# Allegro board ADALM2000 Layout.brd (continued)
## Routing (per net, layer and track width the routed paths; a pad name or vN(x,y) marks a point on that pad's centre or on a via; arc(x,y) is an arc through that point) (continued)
-6V0_AWG_A: length 13.4
  TOP w0.305: v1(25.5,35.06) 25.5,34.87 25.77,34.61 A9.5 ; v1(25.5,28.76) A7.5
  TOP w0.406: v1(25.5,35.06) v1(25.5,35.82)
  BOTTOM w0.305: C273.2 26.2,36.93 ; C273.2 25.71,36.4 ; C273.2 C259.2 ; 24.67,35.56 C275.2 ; C275.2 24.67,36.47 ; C275.2 25.08,36.01 ; 25.71,35.38 C259.2 ; C259.2 26.2,34.74 ; 25.08,35 C277.2 24.67,35.46 ; v1(28.8,29.35) C271.2 27.15,29.35 27.03,29.47 C265.2 C269.2 25.37,28.89 v1(25.5,28.76) ; 24.74,36.64 E13.2 25.35,37.18
-6V0_SC_A: length 34.1
  TOP w0.305: A1.4 27.21,41.93 v1(27.15,41.98) ; v1(27.15,53.92) 27.21,53.87 A4.4 ; v1(25.73,50.93) C81.1 26.51,50.81 C82.1 C83.1 28.44,51.08 v1(28.8,51.08) ; 15.47,49.72 E5.1 16.08,50.26
  BOTTOM w0.305: 29.41,37.47 C138.1 ; C138.1 30.48,37.47 30.73,37.22 C139.1 ; C138.1 29.94,37.96 ; C327.1 20.24,49.61 ; C327.1 19.66,49.06 ; C327.1 19.07,49.61 ; C90.1 33.91,47.12 ; C90.1 32.84,47.12 ; C90.1 33.37,47.62 ; 33.95,48.5 U8.1 ; U8.1 35.7,48.5 U8.PAD ; U8.1 34.7,48.07 ; v1(27.15,41.98) 26.83,42.3 C127.1 C125.1 24.86,42.3 C124.1 v1(23.98,42.18) ; C140.1 32.8,37.22 33.33,36.69 U9.1 34.81,36.69 U9.PAD ; C140.1 32.42,37.63 ; C140.1 31.98,37.22 v1(31.79,37.41) 31.6,37.22 C139.1 ; C139.1 31.15,37.63 ; 33.4,47.94 C93.1 ; C93.1 C91.1 ; C93.1 33.86,48.35 ; v1(23.98,53.86) C67.1 24.86,53.99 C68.1 C70.1 27.09,53.99 v1(27.15,53.92) ; A2.4 28.86,51.14 v1(28.8,51.08) ; C91.1 32.05,48.35 ; C91.1 32.51,47.94
  BOTTOM w0.508: 18.77,49.48 VR1.2
  vias: v1(15.21,49.35) v1(15.97,49.35) v1(20.55,49.73) v1(20.55,49.1) v1(30.39,38.17) v1(31.09,38.17) v1(31.79,38.17) v1(32.36,47.06) v1(32.36,46.43)
-6V0_USR_A: length 14.5
  TOP w0.305: v1(12.93,5.79) 13.05,5.92 A14.2 ; 12.37,5.09 C216.2 11.91,5.5 ; 12.47,5.09 C283.2 12.93,5.5
  BOTTOM w0.305: C133.2 13.05,5.58 ; C133.2 12.52,5.08 ; C133.2 13.59,5.08 ; 20.41,6.3 E16.2 20.95,6.91 ; v1(20.17,7.19) 20.17,8.58 21.82,10.23 R147.2 ; 11.38,5.08 C24.2 ; C24.2 11.91,5.58 ; C24.2 12.44,5.08
  vias: v1(11.91,5.79) v1(20.93,7.19)
GND: length 1042.3
  TOP w0.152: U509.8 U509.PAD
  TOP w0.203: D741.A v1(102.78,35.65) ; v2(38.4,46.96) 38.23,46.96 37.69,46.43 37.69,45.16 38.23,44.63 v2(38.4,44.63) ; 35.65,14.58 U7.4 ; U7.4 36.05,15.3 ; U7.4 36.05,13.87 ; v1(102.72,34.35) D739.A ; U509.PAD 101.25,31.44 U509.4 102.38,30.31 v2(102.41,30.31) ; v1(83.16,57.1) 82.62,56.56 U6.1
  TOP w0.254: U12.5 44.95,11.12 ; U12.5 44.95,9.8 ; U12.5 44.57,10.46 ; v1(64.57,60.32) 64.63,60.39 U14.11 ; U2.5 59.29,49.06 59.58,49.35 v1(59.79,49.35) ; v1(63.35,49.86) 63.35,50.07 63.59,50.31 U2.62 ; U14.15 64.32,59.76 v1(64.57,59.51) ; v1(65.38,58.7) 65.63,58.45 U14.22 ; v1(81.51,52.52) 81.62,52.41 U6.22 ; U14.1 66.63,58.26 v1(66.19,58.7) ; U10.4 56.6,19.37 57,19.76 ; A14.3 14.14,4.71 v1(14.32,4.52) ; U14.3 66.44,59.26 v1(66.19,59.51) ; 45.45,9.8 U12.4 45.45,11.12 ; U2.64 62.59,50.33 62.33,50.07 v1(62.33,49.86) ; v1(71.66,54.3) C66.2 C64.2 ; v1(80.24,52.52) 80.12,52.41 U6.19 ; A4.5 27.86,53.87 v1(27.91,53.92) ; U2.19 58.59,42.31 58.59,42.31 58.59,42.41 59.18,43 ; C44.2 C41.2 ; U518.1 97.35,53.26 v1(96.87,52.78) ; v1(27.91,41.98) 27.86,41.93 A1.5 ; U14.8 66.13,60.39 v1(66.19,60.32) ; 59.59,44.37 59.4,44.56 ; U6.20 80.62,53.54 v1(80.87,53.79) 81.12,53.54 U6.21 ; 66.09,44.37 66.09,44.37
  TOP w0.279: U2.14 58.99,44.56 ; U2.11 59,46.06
  TOP w0.305: 40.17,54.99 C119.2 v1(39.6,55.45) ; R83.1 66.77,64.87 ; R83.1 66.77,63.85 ; R83.1 67.27,64.36 ; 43.71,50.3 C109.2 ; C109.2 v1(44.17,49.77) ; C109.2 44.63,50.3 ; C45.2 v1(67.41,54.3) ; U646.P9 v2(96.76,18.42) ; 70.08,49.4 C41.2 70.48,49.86 ; C180.2 39.8,13.73 ; C180.2 39.34,13.32 ; C180.2 38.89,13.73 ; 57.04,20.9 R2.2 ; R2.2 v1(57.04,22.17) ; R2.2 57.54,21.41 ; v2(66.14,41.22) 66.09,41.27 U2.34 66.09,42.69 ; 20.74,10.06 C214.2 ; C214.2 20.2,10.56 ; C214.2 21.27,10.56 ; C39.2 70.48,51.51 ; 97.72,30.91 C648.1 ; C648.1 98.37,30.26 ; C648.1 97.76,30.3 ; Y1.2 58.94,61.83 ; Y1.2 58.03,60.77 ; Y1.2 58.03,62.88 ; Y1.2 57.13,61.83 ; v1(75.97,15.35) 75.31,14.69 Y578.2 ; 44.21,32.59 C294.2 ; C294.2 v1(44.61,31.95) ; C294.2 C295.2 ; 42.2,22.62 C243.1 ; C243.1 42.84,23.31 ; C243.1 42.2,24.01 ; C257.2 33.44,31.83 C250.2 ; U511.D12 v2(78.07,26.49) ; 40.17,53.97 C115.2 ; C115.2 v1(39.6,54.43) C100.2 C102.2 ; C115.2 40.17,54.89 ; 55.13,46.68 C65.2 ; C65.2 55.41,46.56 v1(54.71,46.56) ; C65.2 55.54,47.14 ; C248.2 38.89,22.93 v1(39.34,22.93) 39.34,23.91 R93.2 ; v1(28.8,48.97) 28.74,49.03 C84.2 ; 72.15,52.46 C64.2 71.66,51.93 ; 7.37,38.67 P1.11 ; P1.11 8.45,39.75 ; P1.11 6.29,39.75 ; P1.11 7.37,40.83 ; C218.2 43.43,21.09 ; C218.2 42.9,21.58 ; C218.2 v1(42.24,21.09) ; 53.44,30.98 R116.2 53.95,31.48 ; C97.2 27.62,21.92 ; C97.2 27.21,22.38 ; C97.2 C96.2 ; U511.J5 v2(84.85,25.36) U511.H6 ; 21.05,62.75 TP7.1 ; TP7.1 21.94,61.86 ; TP7.1 22.83,62.75 ; TP7.1 21.94,63.64 ; 22.71,60.02 C69.2 ; C69.2 23.46,60.69 ; C69.2 21.96,60.69 ; U10.16 55.59,17.87 v1(55.41,18.04) ; U10.16 U10.15 ; U10.16 55.59,16.47 ; P510.9 64.26,2.99 ; P1.6 10.99,47.37 ; P1.6 8.83,47.37 ; P1.6 9.91,46.29 ; C229.2 C233.2 69.12,62.24 v1(69.19,62.3) ; v1(32.87,31.19) C250.2 ; C250.2 C253.2 ; U14.11 64.63,62.76 C227.2 v1(64.68,63.57) ; 21.96,48.75 C128.2 ; C128.2 22.71,48.08 ; C128.2 22.71,49.43 ; C84.2 28.17,49.44 ; C84.2 C86.2 ; 25.85,50.05 C81.2 ; C81.2 26.32,49.98 v1(25.73,49.98) ; C81.2 26.51,50.18 C82.2 ; U12.4 U12.5 ; 41.88,37.22 C154.2 ; C154.2 42.58,37.86 ; C154.2 41.18,37.86 ; C324.2 98.91,39.14 ; C324.2 98.5,38.68 ; C324.2 98.91,38.22 ; 57.2,52.4 R4.2 56.7,52.91 ; 11.79,17.85 D11.1 ; C142.2 32.69,48.91 ; C142.2 32.23,49.31 ; C142.2 31.77,48.91 ; 86.14,54.66 C193.1 86.14,55.73 ; v1(30.45,57.99) C332.2 C331.2 ; 51.38,44.28 C174.2 ; C174.2 52.45,44.28 ; C174.2 51.92,43.76 v1(51.66,43.51) ; C141.2 33.25,49.31 ; C141.2 32.79,48.91 ; C141.2 33.7,48.91 ; 48.27,36.66 A8.4 47.33,36.26 v1(47.27,36.32) ; 80.62,50.65 U6.20 ; U6.20 U6.21 ; U6.20 U6.19 80.12,50.65 ; U10.15 55.09,17.79 v1(54.84,18.04) 54.59,17.79 U10.14 ; U10.15 55.09,16.47 ; U10.15 U10.14 ; R85.1 63.35,63.62 ; R85.1 62.84,64.12 ; R85.1 v1(62.14,63.62) ; v1(54.84,18.62) 54.59,18.87 U10.10 v1(52.3,18.87) ; U511.E7 v2(82.03,23.66) ; R213.2 93.49,36.02 ; 52.35,30.74 C56.2 ; C56.2 52.8,31.15 ; C56.2 53.26,30.74 ; U511.B8 v2(80.33,23.1) ; 12.93,4.05 C283.1 ; C283.1 12.47,4.46 ; C283.1 13.38,4.46 ; C182.2 55.22,23.76 ; C182.2 54.52,23.12 ; C182.2 55.92,23.12 ; U646.G9 92.23,13.89 v2(92.23,13.89) ; U511.J9 v2(83.16,27.06) U511.H8 ; 47.85,17.05 C217.2 ; C217.2 v1(47.15,17.54) 46.96,17.73 U13.6 ; C217.2 v1(48.61,17.54) ; U14.8 66.13,62.26 ; 39.27,44.04 C148.2 C168.2 40.17,43.05 ; v1(25.73,49.15) C87.2 26.51,49.03 C86.2 ; C110.1 49.85,53.79 ; C110.1 v1(49.44,53.16) C112.1 ; C110.1 v1(49.44,54.43) C118.1 49.85,55.06 ; C114.1 C116.1 ; C114.1 v1(46.58,60.78) ; C114.1 47.04,60.21 ; C116.1 45.11,60.21 ; C116.1 v1(45.57,60.78) ; 40.05,51.74 C107.2 ; C107.2 39.43,52.27 ; C107.2 40.05,52.8 ; U511.K4 v2(87.12,25.36) ; 55.42,48.97 R13.2 v1(54.71,48.46) ; 11.79,24.32 D14.1 ; C331.2 v1(30.45,58.87) ; C331.2 31.02,59.64 C330.2 ; C290.2 C288.2 v1(46.58,27.57) ; C55.2 64.06,53.73 ; C55.2 v1(63.6,54.37) ; C55.2 63.14,53.73 ; 49.85,43.51 C169.1 49.44,43.05 ; U511.C5 v2(81.46,21.96) ; Y578.2 75.81,15.25 ; Y578.2 75.78,14.16 ; 44.09,60.21 C120.1 ; C120.1 44.55,60.62 ; C120.1 45.01,60.21 ; A11.3 56.22,28.07 v1(56.28,28.01) ; C242.2 v1(34.77,26.17) ; v2(97.32,8.8) U646.G1 ; C216.1 12.37,4.46 ; C216.1 11.45,4.46 ; C216.1 11.91,4.05 ; 62.39,65.16 C225.2 61.95,64.75 ; 62.39,65.16 62.41,65.16 ; 62.39,65.16 v1(62.58,64.97) ; C82.2 v1(27.28,49.6) C86.2 ; C82.2 C83.2 ; v1(73.63,65.48) C238.2 ; C238.2 72.93,66.01 ; C238.2 72.93,64.94 ; 32.48,29.03 R105.2 31.78,29.06 C260.2 ; C166.2 40.17,41.93 ; C166.2 v1(39.6,41.48) C153.2 ; C166.2 40.17,41.02 ; 96.21,48.26 96.35,48.4 U518.22 ; 81.12,50.65 U6.21 ; U6.21 U6.22 81.62,50.65 ; 12.93,10.27 C323.1 ; C323.1 12.47,10.68 ; C323.1 13.38,10.68 ; 50.77,37.08 R122.1 v1(51.28,37.79) ; D19.1 12.91,35.12 ; D19.1 11.79,35.12 ; D19.1 12.35,35.68 ; 92.05,37.16 GND_5.1 ; GND_5.1 92.94,38.05 ; GND_5.1 93.83,37.16 ; GND_5.1 92.94,36.27 ; U511.P12 v2(84.29,32.71) ; C234.2 C232.2 v1(69.12,57.48) ; C261.2 32.76,35.56 ; C261.2 32.23,36.06 ; C261.2 31.7,35.56 ; U508.B3 v2(69.18,5.29) ; U646.G8 v2(93.36,12.76) ; U511.G5 v2(84.29,23.66) ; 59.72,25.83 Y523.2 ; Y523.2 61.32,25.83 ; Y523.2 60.52,25.08 ; 52.09,32.65 C240.2 ; C240.2 53.12,32.65 v1(53.26,32.51) ; C240.2 52.55,32.24 ; C246.2 C253.2 ; C246.2 v1(32.87,29.66) ; C246.2 33.44,29.21 ; C253.2 v1(32.87,30.43) ; C171.1 45.01,48.27 ; C171.1 v1(44.55,48.84) ; C171.1 44.09,48.27 ; GND_4.1 66.9,20.14 ; GND_4.1 66.9,18.36 ; GND_4.1 66.01,19.25 ; GND_4.1 67.79,19.25 ; 49.44,41.27 C167.1 v1(50.01,41.73) ; S1.4 v1(107.25,28.78) ; S1.4 108.03,27.58 ; S1.4 107.25,26.62 ; U511.L5 v2(87.12,26.49) ; C144.2 31.62,49.15 ; C144.2 31.09,49.65 ; C144.2 30.55,49.15 ; C161.1 47.04,48.27 ; C161.1 v1(46.58,48.84) ; C161.1 46.12,48.27 ; U511.E9 v2(80.33,25.36) ; U518.22 96.35,49.76 ; U518.22 95.95,49.06 ; U646.E2 v2(95.63,8.24) ; C310.2 v1(37.06,64.14) ; C310.2 36.29,64.63 ; C310.2 35.76,64.14 ; 39.6,53.54 v1(39.6,53.67) ; 39.6,53.54 39.72,53.41 C113.2 ; 39.6,53.54 39.47,53.41 C102.2 ; C66.2 72.15,53.48 ; 8.83,39.75 P1.12 ; P1.12 9.91,38.67 ; P1.12 9.91,40.83 ; P1.12 10.99,39.75 ; C113.2 40.17,52.96 ; C113.2 40.17,53.87 ; C4.2 82.71,66.19 ; C4.2 82.71,65.27 ; C4.2 82.31,65.73 ; 42.56,25.03 C245.1 42.07,24.5 ; 98.6,30.23 99.05,29.78 ; 99.05,29.78 98.55,29.28 ; 99.05,29.78 99.54,30.27 ; C176.2 46.26,12.14 C17.2 47.04,12.15 R67.2 47.04,13.66 ; C102.2 39.03,52.96 ; C330.2 30.41,59.76 ; C330.2 v1(30.9,60.42) ; 45.11,48.27 C159.1 ; C159.1 46.02,48.27 ; C159.1 v1(45.57,48.84) ; v1(62.58,67.19) C224.2 ; C224.2 61.95,67.6 ; C224.2 61.49,67.19 ; C112.1 49.85,52.52 ; C112.1 49.44,52.07 ; 21.96,50.46 C71.2 ; C71.2 22.71,51.13 ; C71.2 22.71,49.78 ; 11.91,10.27 C319.1 ; C319.1 11.45,10.68 ; C319.1 12.37,10.68 ; 16.79,5.85 C202.2 ; C202.2 17.7,5.85 ; C202.2 17.24,5.45 ; 95.2,48.26 95.05,48.26 94.85,48.45 U518.19 ; 90.47,19.46 C616.2 90.49,20.19 ; U518.19 95.26,49.06 ; U518.19 94.85,49.76 ; 28.17,49.77 C83.2 ; C83.2 28.62,50.18 ; 84.85,27.06 v2(84.85,26.48) ; U10.14 54.59,16.47 ; 56.34,19.77 U10.4 55.59,19.37 v1(55.41,19.19) ; 54.44,53.59 C121.1 ; C121.1 55.19,52.83 ; C121.1 55.16,53.56 ; 63.79,26.62 C805.2 63.26,27.13 ; C6.2 50.72,20.29 ; C6.2 50.72,19.22 ; C6.2 v1(50.01,19.76) ; 17.63,14.68 17.5,14.55 R158.1 ; C153.2 39.03,41.93 ; C153.2 39.03,41.02 ; C318.2 17.7,11.57 ; C318.2 17.24,11.16 ; C318.2 16.79,11.57 ; U511.N5 v2(88.25,27.62) ; R106.2 30.71,36.65 ; R106.2 30,36.04 ; R106.2 31.42,36.04 ; 39.03,42.03 C151.2 v1(39.6,42.49) C164.2 ; 71.11,13.3 C579.2 ; C579.2 71.15,12.69 ; C579.2 71.85,12.56 v1(71.85,12.27) ; S1.3 108.03,23.98 ; S1.3 107.25,23.03 ; S1.3 107.25,24.93 ; 21.96,38.52 C126.2 ; C126.2 22.71,39.19 ; C126.2 23.46,38.52 ; U646.E1 v2(96.19,7.67) ; U511.A11 v2(77.07,23.8) ; 21.69,30.63 R198.2 ; R198.2 22.71,30.63 ; R198.2 22.2,30.14 ; C247.1 C254.1 ; C247.1 C251.1 v1(42.14,26.24) ; C247.1 v1(42.14,27) ; C254.1 41.44,28.22 ; C254.1 v1(42.14,27.76) ; C260.2 31.78,30.71 ; C260.2 32.33,30.17 ; C5.2 82.08,61.2 ; C5.2 81.18,60.14 ; C5.2 82.08,59.09 ; 17.8,11.57 C322.2 ; C322.2 18.26,11.16 ; C322.2 18.72,11.57 ; v2(38.07,56.56) 38.5,56.14 C98.2 39.19,56.14 ; C117.2 45.64,50.3 ; C117.2 v1(45.18,49.73) ; C117.2 44.73,50.3 ; C311.2 32.92,62.2 ; C311.2 33.42,61.67 ; C311.2 32.92,61.13 ; v1(50.01,42.49) C165.1 49.44,42.95 ; D4.1 15.58,30.8 ; 63.49,64.36 R84.1 ; R84.1 63.98,64.87 ; R84.1 63.98,63.85 ; 14.46,35.12 D3.1 ; D3.1 15.58,35.12 ; D3.1 15.02,35.68 ; 72.36,54.43 GND_6.1 73.25,55.32 ; D8.1 15.58,22.16 ; C96.2 27.62,21.16 ; C96.2 27.21,20.7 ; 34.29,22.5 C256.2 v1(33.75,21.41) ; U646.P1 v2(101.85,13.33) ; v1(47.22,31.06) 47.22,31.12 47.28,31.18 A6.4 48.27,31.58 ; TP5.1 24.99,17.47 ; TP5.1 24.99,15.69 ; TP5.1 25.88,16.58 ; TP5.1 24.1,16.58 ; 91.02,20.71 C617.2 ; C617.2 91.74,20.73 ; C617.2 91.77,21.46 ; U646.B1 v2(94.5,5.98) ; 62.33,26.84 C803.2 62.79,27.25 ; v2(83.16,18) U511.A1 ; U511.D2 v2(84.29,20.27) ; C172.1 52.45,46.93 ; C172.1 51.38,46.93 ; C172.1 51.92,47.57 v1(52.04,47.7) ; 7.37,46.29 P1.5 ; P1.5 8.45,47.37 ; P1.5 6.29,47.37 ; 11.79,30.8 D17.1 ; 9.07,9.22 C308.2 9.57,9.75 ; U518.1 97.76,53.96 ; 78.46,59.3 C196.2 78.99,58.8 ; v2(79.76,16.29) 79.76,16.41 C626.2 ; 44.73,38.36 C170.2 ; C170.2 v1(45.18,37.79) ; C170.2 45.95,38.36 C221.2 v1(46.14,37.77) ; U511.L1 v2(89.17,23.87) ; v1(71.15,14.61) 71.82,14.61 75.08,17.87 v1(75.26,17.87) v1(76.06,18.68) 77.78,20.39 v1(77.95,20.39) ; R123.1 51.37,32.15 ; R123.1 51.98,31.44 ; R123.1 51.37,30.73 ; 33.65,64.21 U17.2 35.69,64.21 ; 69.49,65.6 C223.2 70.08,66.14 ; C164.2 40.17,42.95 ; C164.2 40.17,42.03 ; 9.57,14.27 C297.2 ; C297.2 9.57,15.34 ; C297.2 9.07,14.81 ; R743.1 97.18,56.46 ; R743.1 v1(97.89,55.95) ; R743.1 97.18,55.45 ; U511.H10 v2(81.46,27.62) ; U511.M8 v2(85.99,28.75) ; U511.P2 v2(90.51,26.49) ; 11.79,32.96 D18.1 ; R203.2 v1(77.95,56.97) ; 92.23,12.2 v2(91.67,12.2) ; D5.1 15.58,28.64 ; 33.32,29.06 C244.2 32.82,28.52 ; U511.L11 v2(83.16,30.45) ; 16.91,14.04 R158.1 ; R158.1 16.91,15.06 ; C158.2 43.61,38.36 ; C158.2 43.15,37.96 ; C158.2 42.7,38.36 ; 92.07,30.67 C614.2 92.1,31.4 ; C160.2 v1(44.17,37.79) ; C160.2 44.63,38.36 ; C160.2 43.71,38.36 ; 83.08,58.11 R74.1 82.44,58.62 ; D2.1 15.58,32.96 ; 10.64,10.57 C175.2 11.17,11.07 ; v1(43.15,49.77) C111.2 43.61,50.3 ; L13.1 v1(67.13,66.88) ; L13.1 67.7,65.81 ; L13.1 67.13,65.05 ; v1(63.63,66.88) L14.1 63.63,65.05 ; v1(58.52,34.05) C801.2 ; v1(79.55,59) R75.1 ; C295.2 44.21,33.35 ; C295.2 44.61,33.81 ; U646.T9 v2(97.89,19.55) ; 52.59,50.98 C123.2 ; C123.2 53.31,50.95 ; C123.2 52.56,51.71 ; v1(21.44,20.52) 21.31,20.65 U20.3 19.37,20.65 ; 90.72,52.63 C748.2 v2(90.14,53.16) ; U646.J2 v2(97.89,10.5) ; U646.A9 v2(88.84,10.5) ; 11.79,26.48 D15.1 ; D7.1 15.58,24.32 ; U511.K14 v2(80.89,30.45) ; U511.G3 v2(85.42,22.53) ; U511.N15 v2(81.67,33.63) ; 11.79,20 D12.1 ; U511.K10 v2(83.16,29.32) ; U511.G13 v2(80.33,28.75) ; U511.R9 v2(86.89,31.36) ; 67.76,64.39 C239.2 ; C239.2 68.83,64.39 ; C239.2 68.3,64.89 ; 22.2,28.94 R197.2 21.69,28.44 ; D9.1 15.58,20 ; 10.64,4.98 C179.2 ; 17.8,5.85 C282.2 ; C282.2 18.26,5.45 ; C282.2 18.72,5.85 ; 81.46,24.79 v2(81.46,24.23) ; 95.35,17.68 95.63,17.4 v2(95.63,17.29) 95.63,16.72 U646.M9 ; 72.49,62.56 TP6.1 ; TP6.1 72.49,64.34 ; TP6.1 71.6,63.45 ; TP6.1 73.38,63.45 ; U511.C15 v2(76.01,27.98) ; C105.2 42.2,49.29 ; C105.2 40.8,49.29 ; C105.2 41.5,48.65 ; R124.1 43.74,32.93 ; 37.55,12.18 U7.8 37.96,11.47 ; U646.F9 v2(92.8,13.33) ; 37.89,21.13 C222.2 37.44,21.66 v1(37.18,21.92) ; U646.B3 v2(92.8,7.67) ; U646.T1 v2(102.98,14.46) ; U646.D1 v2(95.63,7.11) ; 5.64,51.15 11.73,51.15 ; D10.1 15.58,17.85 ; v1(58.2,29.22) C795.1 58.9,29.63 ; 11.79,28.64 D16.1 ; 40.45,33.78 R94.2 40.45,34.65 40.03,35.07 C249.2 40.53,35.76 v1(40.74,35.55) ; U646.M1 v2(100.72,12.2) ; R121.1 43.53,37.07 ; C44.2 70.48,50.68 ; 39.17,40.33 C156.2 39.67,40.87 ; R77.1 v1(40.82,17.22) ; v1(50.01,18.62) C3.2 50.72,19.15 ; C600.2 v2(84.87,14.46) ; U511.E5 v2(83.16,22.53) ; D6.1 15.58,26.48 ; U646.D8 v2(92.23,11.63) ; 11.79,22.16 D13.1 ; U646.J8 v2(93.93,14.46) ; U511.F10 v2(80.33,26.49) ; U646.B9 v2(90.54,11.07) ; U14.22 v1(65.63,56.33)
  TOP w0.406: C617.2 91.39,21.14 v2(91.79,21.54) ; v1(91.05,30.61) 91.31,30.61 C614.2 ; C194.1 v1(75.16,54.94) ; 46.77,5.38 C16.2 47.26,5.92 ; v2(90.44,20.34) 90.12,20.01 C616.2 ; R213.2 94.02,35.51 v1(94.21,35.32) ; C193.1 v1(86.84,55.19)
  TOP w0.508: C69.2 22.71,61.67 ; 62.89,11.1 C8.2 63.39,11.63 ; v1(101.49,32.25) U509.PAD v1(99.79,30.54) ; C128.2 23.59,48.75 ; C126.2 v1(22.71,37.54) ; 23.59,50.46 C71.2
  TOP w0.635: C190.2 77.25,50.68 ; C190.2 75.85,50.68 ; C190.2 76.55,50.05 ; 90.33,48.02 C742.2 89.63,47.38 ; C183.2 75.22,50.68 ; C183.2 73.82,50.68 ; C183.2 74.52,50.05 ; 86.97,50.05 C187.2 ; C187.2 87.67,50.68 ; C187.2 86.27,50.68 ; 81.03,11.8 E687.1 80.99,13.02 ; 84.49,50.68 C178.2 ; C178.2 85.19,50.05 ; C178.2 85.89,50.68 ; 90.71,48.02 C738.2 ; C738.2 91.41,47.38 ; C738.2 92.11,48.02 ; C23.2 43.09,8.97 ; C23.2 44.06,8.41 ; C23.2 42.12,8.41 ; 44.88,12.67 C99.2 43.91,12.11 ; C2.1 51.24,15.1 ; C2.1 49.54,15.1 ; C2.1 50.39,14.3 ; 100.49,48.02 C737.2 99.79,47.38 ; 102.75,26.77 102.26,27.27 101.81,26.82 ; 101.83,47.38 C740.2 101.13,48.02 ; 46.96,5.09 C18.2 47.66,4.46
  TOP w0.762: C192.2 33.82,17.51 ; C192.2 33.82,15.4 ; C192.2 34.72,16.46 ; 4.27,5.15 D26.C ; D26.C 5.41,6.42 ; D26.C 4.27,7.69 ; D26.C 3.12,6.42 ; C320.2 91.2,61.22 ; C320.2 89.09,61.22 ; C320.2 90.14,60.32 ; 36.23,16.29 C177.2 ; C177.2 36.23,18.4 ; C177.2 35.33,17.35 ; C600.2 86.76,14.57 ; C600.2 84.98,16.35 ; C600.2 85.12,14.71 ; C191.2 34.72,19 ; C191.2 33.82,17.94 ; C191.2 33.82,20.05 ; 80.57,37.92 C696.2 79.67,38.97 ; D1.A 5.41,12.01 ; D1.A 3.12,12.01 ; D1.A 4.27,10.74 ; D1.A 4.27,13.28 ; 88.78,61.22 C321.2 87.73,60.32
  TOP w0.889: 54.32,14.68 C12.2 51.8,14.68 ; 56.11,15.73 C9.2 54.85,14.68
  TOP w1.016: 27.66,34.99 A9.PAD 27.66,32.72 ; 34.81,13.6 C186.2 33.75,14.5 ; 27.66,26.88 A7.PAD 27.66,29.14
  TOP w1.27: 86.33,40.98 C663.2 ; C663.2 86.33,43.5 ; C663.2 87.39,42.24
  L5_SIG w0.305: 8.83,47.37 P1.6 ; P1.6 10.99,47.37 ; P1.6 9.91,48.45 ; P1.6 9.91,46.29 ; P1.11 7.37,40.83 ; P1.11 8.45,39.75 ; P1.11 6.29,39.75 ; P1.11 7.37,38.67 ; TP6.1 72.49,64.34 ; TP6.1 72.49,62.56 ; TP6.1 73.38,63.45 ; 9.91,38.67 P1.12 ; P1.12 8.83,39.75 ; P1.12 9.91,40.83 ; P1.12 10.99,39.75 ; 63.47,2.21 P510.9 64.26,2.99 ; 72.36,54.43 GND_6.1 ; GND_6.1 74.14,54.43 ; GND_6.1 73.25,53.54 ; GND_6.1 73.25,55.32 ; 92.94,36.27 GND_5.1 ; GND_5.1 93.83,37.16 ; GND_5.1 92.94,38.05 ; 24.99,15.69 TP5.1 ; TP5.1 24.99,17.47 ; TP5.1 24.1,16.58 ; 21.94,61.86 TP7.1 ; TP7.1 22.83,62.75 ; TP7.1 21.94,63.64 ; TP7.1 21.05,62.75 ; P1.5 8.45,47.37 ; P1.5 6.29,47.37 ; P1.5 7.37,48.45 ; P1.5 7.37,46.29 ; 62.2,2.21 P510.7
  L6_SIG w0.305: TP7.1 22.83,62.75 ; TP7.1 21.05,62.75 ; TP7.1 21.94,61.86 ; GND_5.1 92.94,38.05 ; GND_5.1 93.83,37.16 ; GND_5.1 92.94,36.27 ; 63.47,2.21 P510.9 64.26,2.99 ; 66.01,19.25 GND_4.1 ; P1.6 10.99,47.37 ; P1.6 9.91,46.29 ; P1.6 9.91,48.45 ; P1.6 8.83,47.37 ; TP6.1 72.49,64.34 ; TP6.1 73.38,63.45 ; TP6.1 72.49,62.56 ; TP6.1 71.6,63.45 ; 6.29,47.37 P1.5 ; P1.5 7.37,46.29 ; P1.5 7.37,48.45 ; P1.5 8.45,47.37 ; 72.36,54.43 GND_6.1 ; GND_6.1 73.25,55.32 ; GND_6.1 74.14,54.43 ; TP5.1 24.99,17.47 ; TP5.1 24.1,16.58 ; TP5.1 25.88,16.58 ; TP5.1 24.99,15.69 ; P1.11 7.37,40.83 ; P1.12 9.91,40.83 ; 62.2,2.21 P510.7
  BOTTOM w0.254: v1(79.6,55.06) 79.35,55.32 C199.2
  BOTTOM w0.305: C792.2 76.42,27.57 v2(76.01,27.98) ; C792.2 76.75,27.24 ; C792.2 76.1,27.89 ; C792.2 76.13,27.28 ; 86.13,54.68 R92.2 ; R92.2 v1(86.84,55.19) ; R92.2 86.13,55.7 ; 58.45,49.45 C63.2 ; C63.2 58.45,50.52 ; C63.2 58.95,49.98 ; 66.14,41.11 C7.2 66.55,40.65 ; C213.2 28.36,24.77 v1(28.17,24.97) C258.2 ; C213.2 29.72,24.77 ; C213.2 29.18,25.26 ; C204.2 55.16,57.76 ; C204.2 v1(55.16,56.46) C22.2 ; C204.2 54.66,57.22 ; v1(23.98,54.74) C67.2 24.86,54.62 C68.2 ; C106.1 48.68,59.89 ; C106.1 48.04,60.59 ; C106.1 48.04,59.13 47.98,59.13 v1(47.72,58.87) ; 93.44,14.09 93.73,13.8 ; 93.44,14.09 93.81,14.46 v2(93.93,14.46) ; 93.44,14.09 93.12,13.77 ; C271.1 v1(28.04,30.93) C270.2 ; 88.14,9.69 88.47,10.01 ; 88.47,10.01 88.18,10.3 ; 88.47,10.01 88.84,10.39 v2(88.84,10.5) ; C37.2 70.04,48.59 ; C37.2 69.63,49.05 ; C37.2 69.63,48.13 ; 97.08,52.52 C745.1 ; C745.1 97.59,52.53 R766.1 ; C745.1 97.58,51.99 ; 54.54,45.41 C33.2 ; C33.2 v1(55.03,44.65) C28.2 ; C33.2 55.03,45.95 ; U8.12 38.65,48.15 v1(38.33,47.83) ; C62.2 63.55,51.19 ; C62.2 63.09,50.78 ; C62.2 62.63,51.19 ; Q4.1 20.69,12.23 ; Q4.1 19.99,11.58 ; Q4.1 20.69,10.93 ; v2(88.25,27.62) 88.25,28.08 C713.2 ; C230.2 64.04,62.24 ; C230.2 64.68,61.54 ; C230.2 64.04,60.84 ; 31.15,36.18 C139.2 ; C139.2 29.95,36.59 C138.2 ; C139.2 v1(31.79,36.59) C140.2 32.42,36.18 ; C22.2 54.66,55.7 ; C22.2 55.16,55.17 ; 30.77,22.86 C287.2 ; C287.2 30.78,23.31 v1(30.78,22.55) C285.2 30.28,21.79 ; C287.2 30.36,23.31 ; 95.28,56.49 C756.1 95.78,55.95 ; R208.2 83.54,54.51 ; R208.2 82.52,54.51 ; R208.2 83.03,54.01 ; R46.2 21.31,48.53 ; R46.2 21.21,48.02 C134.2 19.21,48.02 v1(18.9,47.7) ; R46.2 22.02,47.92 ; v2(89.74,30.66) 89.74,30.34 C633.2 89.06,30.24 ; C589.2 69.21,5.32 v2(69.18,5.29) ; C589.2 69.62,5.8 ; C589.2 69.21,6.26 ; 58.33,47.11 C38.2 ; C38.2 58.33,48.03 ; C38.2 58.74,47.57 ; 27.15,31.64 27.14,31.63 C274.2 ; 27.15,31.64 v1(27.15,30.93) C263.1 ; 27.15,31.64 C270.2 ; v2(34.71,29.51) C299.2 34.2,30.05 ; C46.2 64.57,51.19 ; C46.2 63.65,51.19 ; C46.2 64.11,50.78 ; TP7.1 21.94,63.64 ; TP7.1 22.83,62.75 ; TP7.1 21.94,61.86 ; TP7.1 21.05,62.75 ; 94.64,5.88 C643.2 94.97,5.5 v2(94.5,5.98) ; C259.1 C273.1 ; C259.1 27.79,35.38 ; C259.1 27.08,34.85 ; C273.1 27.08,36.93 ; C273.1 27.79,36.4 ; v2(90.54,11.07) 90.06,10.59 C641.2 ; 71.6,10.03 R594.2 71.09,10.52 ; v1(99.73,36.4) 99.83,36.5 Q512.2 100.67,35.54 ; 73.56,50.85 C21.2 74.06,51.38 ; C48.2 58.33,47.01 ; C48.2 58.33,46.1 ; C48.2 58.74,46.56 ; 96.39,7.01 C652.2 ; C652.2 96.3,7.67 v2(96.19,7.67) ; C652.2 97,6.97 ; GND_4.1 66.9,20.14 ; GND_4.1 67.79,19.25 ; GND_4.1 66.01,19.25 ; GND_4.1 66.9,18.36 ; 61.06,56.8 C228.2 ; C228.2 61.59,57.29 ; C228.2 60.53,57.29 ; 80.24,28.26 C710.2 79.77,28.67 ; C91.2 C93.2 33.4,49.39 ; C91.2 32.51,49.39 ; C91.2 32.05,48.98 ; 16.35,51.43 C329.2 ; C329.2 16.35,52.6 ; C329.2 16.89,52.02 ; C212.2 46.63,23.44 ; C212.2 46.13,22.91 ; C212.2 46.13,23.98 ; 29.37,25.85 C291.2 30.01,25.16 ; 16.52,47.19 R154.2 16.02,46.68 ; GND_10.1 40.49,13.16 ; GND_10.1 41.25,12.39 ; GND_10.1 39.72,12.39 ; GND_10.1 40.49,11.63 ; 40.87,49.95 R82.2 41.38,50.44 ; C296.2 34.83,32.14 v1(34.64,31.95) ; v1(24.05,39.13) C211.2 ; 23.42,56.6 C185.2 22.83,56.05 ; C152.2 40.17,38.68 v1(39.53,38.68) 38.96,38.68 38.27,37.99 U9.10 ; C30.2 62.46,56.25 ; C30.2 62.99,55.76 ; C30.2 61.92,55.76 ; v1(61.36,30.99) 60.98,30.6 R800.2 ; GND_6.1 73.25,55.32 ; GND_6.1 72.36,54.43 ; GND_6.1 74.14,54.43 ; C36.2 67.6,49.79 C31.2 ; C36.2 67.19,50.49 ; C36.2 67.6,50.95 ; 31.9,35.8 Q9.2 32.66,34.85 ; 24.92,31.63 C276.2 ; C276.2 C274.2 ; C276.2 v1(25.37,30.93) C269.1 ; P1.11 7.37,40.83 ; P1.11 7.37,38.67 ; P1.11 8.45,39.75 ; P1.11 6.29,39.75 ; 93.63,50.97 C746.1 ; C746.1 94.12,51.51 ; C746.1 93.63,52.04 ; C235.2 65.7,56.4 v1(65.63,56.33) ; C235.2 C231.2 ; C235.2 66.1,57.1 ; C328.2 17.44,47.65 ; C328.2 17.44,46.73 ; C328.2 17.03,47.19 ; 77.8,33.22 C702.2 77.82,33.95 ; 70.33,14.64 C588.2 v1(70.5,13.83) ; P1.5 7.37,48.45 ; P1.5 6.29,47.37 ; P1.5 8.45,47.37 ; P1.5 7.37,46.29 ; 74.55,22.88 C789.2 ; C789.2 74.84,22.5 v2(74.46,22.89) 74.08,23.27 C790.2 ; C789.2 75.3,22.12 ; C789.2 74.57,22.15 ; C789.2 74.93,22.42 v2(75.31,22.04) 75.69,21.65 C596.2 ; 55.66,29.82 C309.1 56.12,29.41 ; R593.2 70.08,10.52 ; v1(26.96,44.33) 26.83,44.46 C135.2 C136.2 24.6,44.46 C137.2 24.38,44.45 v1(23.72,44.45) ; C207.2 v1(81.51,55.06) ; C207.2 82.04,55.77 ; C207.2 80.97,55.77 ; 23.63,36.01 C275.1 ; C275.1 C277.1 ; C275.1 24.04,36.47 ; C29.2 v1(70.2,56.08) ; C29.2 70.74,55.38 ; C29.2 69.67,55.38 ; 65.63,50.78 C51.2 ; C51.2 66.09,51.19 ; C51.2 65.17,51.19 ; 24.99,15.69 TP5.1 ; TP5.1 24.99,17.47 ; TP5.1 25.88,16.58 ; TP5.1 24.1,16.58 ; 66.86,49.54 C31.2 ; C31.2 67.35,49.01 ; C712.2 78.32,31.3 v2(78.35,31.3) ; C712.2 77.7,31.24 ; C712.2 77.66,30.63 ; 103.99,29.03 C644.2 103.84,29.83 ; 37.89,20.37 C284.2 ; C284.2 v1(37.18,20.9) ; C284.2 37.89,21.44 ; 88.69,20.94 R634.2 ; R634.2 89.41,21.66 ; R634.2 89.4,20.95 ; 97.08,11.32 C645.2 97.45,10.93 v2(97.89,10.5) ; C650.1 97.65,9.13 v2(97.32,8.8) ; C650.1 97.98,8.81 ; C650.1 97.37,8.84 ; v1(46.58,64.46) 46.58,65.23 ; v1(46.58,64.46) 45.82,64.46 ; v1(46.58,64.46) 46.58,63.7 ; v1(46.58,64.46) 47.34,64.46 ; C292.2 38.77,22.93 v1(39.34,22.93) ; 51.57,38.5 Q3.1 ; Q3.1 52.22,37.8 ; Q3.1 52.87,38.5 ; Q3.1 52.22,39.2 ; C43.2 58.33,49.05 ; C43.2 58.74,48.59 ; C43.2 58.33,48.13 ; C699.2 93.88,31.09 ; C699.2 94.38,30.55 ; C699.2 93.88,30.02 ; R165.2 33.12,65.1 ; R165.2 32.59,65.66 ; R165.2 32.59,64.54 ; C270.2 29.06,31.64 R199.2 ; 54.97,39.74 C20.2 ; C20.2 54.97,40.8 ; C20.2 54.33,40.27 ; v1(65.38,58.7) 65.7,58.38 C231.2 ; 85.75,43.91 C667.2 86.25,43.38 ; 53.12,25.38 C298.2 ; C298.2 52.66,25.79 ; C298.2 53.58,25.79 ; C665.2 83.16,27.25 v2(83.16,27.06) ; R43.2 19.88,39.1 C131.2 ; R43.2 21.89,39.1 ; R43.2 21.18,38.49 ; 55.7,19.19 C1.2 56.23,18.7 ; 29.82,40.88 R80.2 29.93,40.27 C219.2 30.71,40.84 v1(30.58,40.97) ; v2(86.98,19.7) 87.45,20.16 C607.2 ; C79.2 24.86,56.53 C80.2 v1(23.98,56.4) ; C79.2 C78.2 ; C79.2 25.63,56.12 ; 9.51,12.77 R138.2 ; R138.2 9.02,13.28 ; R138.2 9.51,13.79 ; 23.56,18.62 R141.2 v1(24.05,17.85) ; 20.34,21.03 A13.PAD ; 44.22,50.11 R31.1 44.71,50.62 ; 58.46,50.8 C35.2 58.86,51.25 ; C668.2 83.86,28.96 83.5,29.32 v2(83.16,29.32) ; 93.56,13.41 C649.2 ; C649.2 93.48,12.76 v2(93.36,12.76) ; C649.2 94.17,13.45 ; C78.2 27.04,56.53 v1(27.18,56.39) ; C78.2 26.52,56.12 ; R747.2 95.99,53.49 ; R747.2 94.97,53.49 ; R747.2 95.48,53 ; v1(65.38,11.25) 65.38,12.01 ; v1(65.38,11.25) 66.14,11.25 ; v1(65.38,11.25) 65.38,10.49 ; v1(65.38,11.25) 64.62,11.25 ; v2(102.98,14.46) 102.98,14.35 C655.2 ; C13.2 48.37,8.71 ; C13.2 47.46,8.71 ; C13.2 47.92,9.12 ; C61.2 55.28,49.05 ; C61.2 54.87,48.59 ; C61.2 55.28,48.13 ; C692.1 84.92,19.63 v2(84.29,20.27) ; C692.1 84.64,19.92 ; C692.1 84.6,19.31 ; 39.97,45.7 C333.2 40.03,46.3 v1(40.03,46.94) ; C70.2 26.52,55.03 ; C70.2 C68.2 ; C70.2 26.83,54.62 v1(27.15,54.94) ; 68.53,55.38 C25.2 ; C25.2 69.59,55.38 ; C25.2 69.06,55.95 69.19,56.08 v1(69.44,56.08) ; R8.2 56.31,18.24 ; R8.2 56.31,17.22 ; R8.2 55.73,17.73 v1(55.41,18.04) 55.34,18.11 ; P1.6 9.91,48.45 ; P1.6 9.91,46.29 ; P1.6 10.99,47.37 ; P1.6 8.83,47.37 ; 99.8,30.54 v1(99.79,30.54) 99.97,30.36 100.24,30.36 C657.2 100.63,31.05 C660.2 99.92,31.18 ; 80.24,55.28 R204.2 80.75,55.78 ; C197.2 85.38,58.11 ; C197.2 84.75,57.41 ; C197.2 84.75,58.81 ; C32.2 66.26,42.39 ; C32.2 66.26,41.32 ; C32.2 66.76,41.86 ; 67.6,53.08 C58.2 ; C58.2 67.6,54 ; C58.2 67.19,53.54 ; GND_9.1 91.03,58.37 ; GND_9.1 90.27,57.6 ; GND_9.1 91.03,56.84 ; GND_9.1 91.79,57.6 ; C27.2 58.08,42.45 ; C27.2 57.59,41.92 ; C27.2 58.08,41.39 ; 17.98,11.38 C316.2 ; C316.2 18.51,10.89 ; C316.2 19.05,11.38 ; C268.2 v1(25.5,25.09) ; C268.2 C264.2 ; C268.2 25.04,25.66 ; v1(27.65,44.78) 27.65,45.22 27.56,45.31 A2.15 ; 98.6,30.35 99.05,29.9 ; 99.05,29.9 99.5,29.46 ; 99.05,29.9 99.54,30.4 ; 99.05,29.9 98.55,29.41 ; C669.2 84.43,25.78 v2(84.85,25.36) ; 70.55,51.64 C50.2 C49.2 ; 73.69,29.91 C683.2 73.63,29.31 v2(73.63,28.78) 73.63,28.61 73.63,28.23 C679.2 73.69,27.64 ; C24.1 12.44,4.21 ; C24.1 11.38,4.21 ; C24.1 11.91,3.71 ; TP6.1 73.38,63.45 ; TP6.1 72.49,64.34 ; TP6.1 72.49,62.56 ; TP6.1 71.6,63.45 ; 63.47,2.21 P510.9 64.26,2.99 ; 43.91,32.88 U11.8 41.67,32.88 v1(41.37,32.59) ; 30.77,24.66 C293.2 30.36,24.2 ; 57.8,40.59 C42.2 ; C42.2 58.2,40.13 ; C42.2 58.2,41.04 ; 16.58,11.38 C314.2 ; C314.2 17.65,11.38 ; C314.2 17.12,10.89 ; C57.2 55.28,47.01 ; C57.2 55.28,46.1 ; C57.2 v1(54.71,46.56) ; 92.05,56 R760.1 92.56,56.5 ; C258.2 C262.2 ; C258.2 28.7,25.67 ; 33.37,45.75 C90.2 33.91,46.24 ; v1(41.83,24.27) 41.87,24.27 41.89,24.29 41.89,24.39 ; 60.53,55.76 C26.2 ; C26.2 61.59,55.76 ; C26.2 61.06,56.25 ; 45.27,7.44 R12.2 45.77,7.95 ; 60.6,51.19 C40.2 ; C40.2 C59.2 ; C40.2 61.06,50.78 ; C49.2 70.14,50.29 ; C49.2 70.55,50.75 ; C807.2 63.37,30.1 ; C807.2 62.3,30.1 ; C807.2 62.84,30.6 ; v2(95.63,17.29) 95.63,16.61 95.54,16.52 ; C231.2 66.1,57.86 ; 67.19,52.52 C54.2 ; C54.2 67.6,52.98 ; C54.2 67.6,52.07 ; 47.6,10.07 R69.2 ; R69.2 48.11,10.57 ; R69.2 47.09,10.57 ; R590.2 70.37,7.19 ; R590.2 69.87,6.63 v1(70.2,6.3) ; R590.2 69.87,7.69 ; 23.67,11.58 Q5.1 ; Q5.1 24.37,10.93 ; Q5.1 25.07,11.58 ; Q5.1 24.37,12.23 ; C709.2 86.78,31.24 v2(86.89,31.36) ; 79.52,35.65 C706.2 ; C706.2 80.25,35.68 ; C706.2 79.5,34.92 ; R587.2 v1(71.15,14.61) ; R587.2 70.35,14.69 ; R587.2 71.07,15.41 ; 22.45,39.67 C338.2 ; C336.2 22.83,55.1 ; v2(90.14,53.16) 90.27,53.16 90.52,53.41 R764.2 ; 103.92,19.94 C615.2 ; C615.2 104.31,19.56 v1(104.87,19) ; C615.2 104.65,19.91 ; C615.2 104.67,19.18 ; v1(80.87,4.54) Q2.2 ; Q2.2 82.6,4.54 ; Q2.2 81.84,3.59 ; C334.2 40.68,49.68 ; C334.2 41.08,49.22 ; C334.2 40.68,48.76 ; U9.12 38.03,36.69 v1(38.45,36.27) 38.52,36.21 C150.2 C149.2 40.87,36.21 C205.2 40.99,36.47 v1(40.99,37.16) ; 80.52,21.91 C686.2 81.24,21.94 ; 21.25,59.7 C74.2 ; C74.2 20.61,60.4 ; C74.2 21.25,61.1 ; 16.58,5.73 C14.2 17.12,5.24 ; C327.2 19.66,51.16 ; C327.2 20.24,50.61 ; C327.2 19.07,50.61 ; C607.2 87.85,19.81 ; C607.2 87.12,19.79 ; C607.2 87.88,20.54 ; 8.83,39.75 P1.12 ; P1.12 9.91,40.83 ; P1.12 10.99,39.75 ; C651.2 96.35,6.97 ; C651.2 96.39,6.36 ; C651.2 95.64,7.11 v2(95.63,7.11) ; 37.88,21.59 C286.2 ; C286.2 37.48,22.04 ; C286.2 37.88,22.5 ; C286.2 37.76,21.92 v1(37.18,21.92) ; 37.53,10.54 R70.2 ; R70.2 38.14,11.25 ; R70.2 37.53,11.96 ; 80.63,25.22 C674.2 ; C674.2 80.66,24.5 ; C674.2 81.38,24.47 ; R206.2 78.84,54.51 ; R206.2 78.33,54.01 ; R206.2 77.82,54.51 ; 67.6,51.05 C34.2 ; C34.2 67.19,51.51 ; C34.2 67.6,51.97 ; 92.94,36.27 GND_5.1 ; GND_5.1 93.83,37.16 ; GND_5.1 92.05,37.16 ; U19.2 U19.1 35.34,25.92 35.09,26.17 v1(34.77,26.17) ; 78.76,20.53 C599.2 v2(79.4,20.46) C598.2 79.47,19.82 ; 11.15,9.81 C315.1 ; C315.1 10.61,10.3 ; C315.1 11.68,10.3 ; C264.2 v1(26.39,25.09) ; C264.2 27.27,25.66 C262.2 ; 16.76,50.43 VR1.1 ; VR1.1 17.78,50.94 ; VR1.1 18.8,50.43 ; C790.2 74.45,22.97 ; C790.2 73.7,23.73 ; C790.2 73.73,23 ; v1(20.29,19) 20.42,18.87 20.8,18.87 21.07,19.14 A13.4 20.66,19.47 ; 89.15,23.8 C618.2 89.13,23.07 ; C641.2 90.41,10.19 ; C641.2 90.44,10.92 ; 75.4,22.03 C596.2 ; C596.2 75.43,21.3 ; C705.2 v2(84.12,35.08) C707.2 ; C133.1 13.59,4.21 ; C133.1 13.05,3.71 ; C133.1 12.52,4.21 ; C262.2 v1(27.28,24.97) ; v2(84.29,32.71) 83.99,32.71 C711.2 ; C59.2 62.28,51.19 ; C59.2 61.82,50.78 ; 75.3,12.17 C675.2 75.28,12.9 ; 71.79,29.92 C597.2 71.29,29.38 ; v1(36.99,28.33) C206.2 36.99,26.97 ; 19.78,38.36 C131.2 ; C131.2 19.09,39 ; A2.7 v1(30.81,51.13) ; 77.56,32.99 C698.2 76.83,32.96 ; 24.17,24.04 C301.2 23.71,23.63 ; 54.87,47.57 C53.2 ; C53.2 55.28,48.03 ; C53.2 55.28,47.11 ; 32.66,29.77 Q8.2 31.9,28.81 ; R764.2 91.1,53.87 ; R764.2 91.1,52.96 ; v1(29.69,51.13) 29.51,51.31 A2.5 ; 33.5,35.04 R200.2 32.99,34.54 ; 91.23,33.76 C701.2 v2(90.74,33.09) ; C68.2 25.63,55.03 ; 79.26,34.69 C700.2 78.53,34.66 ; 59.54,56.4 C226.2 60.23,57.03 ; 41.18,47.95 C335.2 40.68,48.52 v1(40.61,48.59) ; 62.2,2.21 P510.7 ; 24.92,30.11 C269.1 ; C269.1 C265.1 v1(26.26,30.93) C274.2 ; 77.44,23.56 C793.2 78.05,23.53 ; v1(91.74,18.77) 92.03,18.48 R661.2 ; C317.1 13.21,10.3 ; C317.1 12.67,9.81 ; C317.1 12.14,10.3 ; 44.46,38.68 R57.1 43.96,38 v1(44.17,37.79) ; U8.10 39.29,49.8 v1(39.47,49.98) 39.85,50.37 39.85,50.56 C220.2 39.98,50.28 ; v1(41.37,30.05) 41.61,30.28 U11.12 43.91,30.28 ; 29.94,36.1 C138.2 ; C138.2 29.41,36.59 ; C277.1 23.47,35 ; C277.1 24.04,34.54 ; 21.54,8.64 C209.2 ; C209.2 22.07,9.14 ; C209.2 22.6,8.64 ; U18.2 v1(43.58,23.44) ; 72.92,4.77 R583.2 ; C340.2 v1(22.45,47.83) ; C300.2 25.06,24.04 ; 5.64,51.15 11.73,51.15 ; C753.1 99.95,54.12 ; v1(48.17,48.84) C155.1 ; 43.49,59.76 C108.1 43.98,60.3 ; v1(44.55,48.84) 44.11,48.4 C157.1 ; 71.79,27.65 C666.2 ; v1(40.23,28.46) 40.68,28.01 40.68,27.62 R120.2 ; 18.67,5.73 C47.2 18.13,5.24 ; v1(23.98,42.95) 24.63,42.95 C124.2 24.86,42.94 C125.2 C127.2 27.09,42.94 v1(27.15,43) ; 21.37,50.75 C77.2 22.11,50.85 R21.2 21.18,52.14 ; 70.04,49.86 C60.2 69.63,49.4 ; v1(105.77,15.26) R636.2 ; 43.62,47.83 C157.1 ; C157.1 44.11,47.29 ; 21.34,59.59 R18.2 20.73,58.87 ; 96.09,53.48 C751.1 96.62,52.99 ; C210.2 v1(28.35,39.06) ; R214.2 v1(85.82,5.08) ; v2(85.99,28.75) 85.44,29.3 C671.2 ; v2(97.89,19.55) 97.26,18.93 C639.2 97.2,18.86 v2(96.76,18.42)
  BOTTOM w0.406: R593.2 v1(69.31,10.03) ; R117.1 53.28,29.47 v1(53.88,29.47) ; 36.09,24.33 U19.2 34.64,24.33 34.46,24.52 v1(34.46,24.59) ; C704.2 v2(88.74,33.09) C708.2 ; C666.2 71.79,28.72 v2(71.73,28.78) 71.79,28.83 C597.2 ; R583.2 v1(73.63,5.28) ; U18.1 42.7,25 ; U18.1 41.89,24.39 ; U18.1 U18.2 41.95,23.44 ; U18.1 43.45,24.39 ; v2(81.67,33.63) 81.83,33.79 82.06,33.79 C703.2 ; v2(81.46,27.62) 81.9,27.18 C673.2 ; v1(76.12,12.05) C675.2 ; C700.2 78.88,34.39 v2(79.34,34.85) 79.79,35.3 C706.2 ; v2(84.85,25.36) 85.07,25.36 C672.2 ; 34.59,25.28 U19.1 36.09,25.28 ; C698.2 77.18,32.69 v2(77.64,33.14) 78.09,33.6 C702.2
  BOTTOM w0.508: R594.2 R593.2 ; 95.05,32.46 v2(95.22,32.46) ; 94.14,31.33 C678.2
  BOTTOM w0.635: 75.07,48.52 C215.2 74.01,49.43
  BOTTOM w0.762: C769.2 95.79,45.48 ; C769.2 95.1,46.11 ; C769.2 94.4,45.48 ; 96.05,45.48 C774.2 ; C774.2 97.45,45.48 ; C774.2 96.75,46.11 ; 95.05,32.46 C678.2 94.14,33.51 ; C676.2 69.19,31.1 ; C676.2 70.45,30.05 ; C676.2 67.93,30.05 ; C676.2 69.19,28.99 ; 91.76,45.86 C758.2 ; C758.2 93.86,45.86 ; C758.2 92.81,46.76 ; C788.2 70.11,19.51 ; C788.2 69.96,21.14 ; C788.2 68.33,21.29 ; 90.4,46.76 C754.2 91.45,45.86 ; C595.2 72.39,18.72 ; C595.2 70.75,18.86 ; C595.2 70.9,17.23 ; C595.2 72.53,17.08 ; 71.52,25.85 C664.2 ; C664.2 72.43,24.8 ; C664.2 72.43,26.91 ; C278.2 80.81,48.4 ; C278.2 79.41,48.4 ; C278.2 80.11,49.03 ; C680.2 78.56,19.47 ; C680.2 77.07,17.98 ; C680.2 77.18,19.36 ; C289.2 41.95,26.11 ; 84.96,16.36 C637.2 ; C637.2 86.74,14.58 ; C637.2 85.11,14.72 ; 100.85,45.48 C762.2 99.79,46.38 ; C279.2 82.46,48.4 ; C279.2 81.76,49.03 ; C279.2 81.06,48.4 ; 102.21,46.38 C761.2 101.15,45.48 ; 80.57,37.67 C697.2 79.67,38.72
  BOTTOM w0.889: 51.8,14.68 C12.2 ; C12.2 53.06,15.73 ; C12.2 54.32,14.68 ; C9.2 56.11,15.73 ; C9.2 54.85,14.68 ; C9.2 57.36,14.68
  BOTTOM w1.016: C192.2 34.72,16.46 ; C192.2 33.82,15.4 ; C192.2 33.82,17.51 ; 36.36,16.42 C19.2 ; C19.2 36.36,18.53 ; C19.2 35.46,17.47 ; C670.2 87.13,41.6 ; 33.82,17.94 C191.2 ; C191.2 34.72,19 ; C191.2 33.82,20.05 ; 42.86,12.46 C101.2 ; C101.2 43.91,11.55 ; C101.2 44.97,12.46 ; 87.98,49.55 C208.2 89.04,48.65
  vias: v1(1.12,64.08) v1(1.12,60.53) v1(1.12,51.38) v1(1.12,49.86) v1(1.12,48.33) v1(1.12,46.81) v1(1.12,45.29) v1(1.12,43.76) v1(1.12,42.24) v1(1.12,40.71) v1(1.12,39.19) v1(1.37,8.71) v1(1.37,6.93) v1(1.37,5.15) v1(1.62,59) v1(1.62,56.97) v1(1.62,54.94) v1(1.62,52.91) v1(1.62,14.3) v1(1.62,12.52) v1(1.62,10.74) v1(2.64,6.42) v1(4.29,13.79) v1(4.29,10.36) v1(4.29,8.2) v1(5.71,39) v1(5.69,12.01) v1(6.07,6.49) v1(6.2,4.39) v1(6.7,65.1) v1(7.21,55.19) v1(7.21,54.18) v1(7.72,4.14) v1(8.23,65.1) v1(8.23,56.21) v1(8.74,9.34) v1(9.24,14.04) v1(9.24,3.88) v1(9.5,54.43) v1(9.75,65.1) v1(9.75,56.72) v1(10.39,10.23) v1(10.39,3.76) v1(10.51,4.65) v1(11.02,54.43) v1(11.02,45.79) v1(11.28,65.61) v1(11.28,56.72) v1(11.28,3.63) v1(11.53,49.86) v1(11.53,47.32) v1(11.78,40.21) v1(11.91,10.11) v1(12.04,45.54) v1(12.16,3.5) v1(12.29,42.24) v1(12.55,54.43) v1(12.55,49.35) v1(12.55,46.3) v1(12.55,39.44) v1(12.8,65.61) v1(12.8,56.72) v1(12.8,44.52) v1(13.05,3.38) v1(13.31,41.48) v1(13.43,10.11) v1(13.56,48.33) v1(13.56,45.29) v1(13.82,58.49) v1(13.82,43.51) v1(14.07,56.72) v1(14.07,54.43) v1(14.07,3.38) v1(14.32,65.61) v1(14.32,47.57) v1(14.32,40.46) v1(14.58,44.27) v1(14.83,42.49) v1(15.09,39.44) v1(15.59,54.43) v1(15.59,46.3) v1(15.59,43.25) v1(15.59,3.12) v1(15.85,66.11) v1(15.85,56.72) v1(15.85,41.48) v1(16.36,52.78) v1(16.48,51.25) v1(16.61,57.73) v1(16.61,54.43) v1(16.61,45.29) v1(16.61,42.49) v1(16.74,47.19) v1(16.86,40.46) v1(17.12,59) v1(17.12,53.16) v1(17.12,52.02) v1(17.12,3.12) v1(17.24,10.68) v1(17.24,5.03) v1(17.37,66.11) v1(17.75,39.57) v1(17.88,15.57) v1(18.26,10.68) v1(18.26,5.03) v1(18.39,60.65) v1(18.39,59.38) v1(18.39,51.64) v1(18.64,2.87) v1(18.9,66.11) v1(19.28,11.44) v1(19.66,51.64) v1(19.91,10.68) v1(20.17,15.57) v1(20.17,2.87) v1(20.42,66.62) v1(20.42,60.78) v1(20.42,59.38) v1(20.55,51.64) v1(20.55,50.75) v1(20.93,52.14) v1(21.18,61.8) v1(21.18,38.3) v1(21.31,8.71) v1(21.56,49.73) v1(21.56,49.1) v1(21.88,29.16) v1(21.94,66.62) v1(21.94,2.61) v1(22.32,21.28) v1(22.32,20.52) v1(22.45,39.44) v1(22.45,15.57) v1(22.58,55.57) v1(22.58,34.62) v1(22.71,61.8) v1(22.71,49.6) v1(22.83,8.71) v1(23.4,36.21) v1(23.4,35.44) v1(23.47,66.11) v1(23.47,59.38) v1(23.72,60.78) v1(23.72,49.6) v1(23.72,48.71) v1(23.72,3.12) v1(24.1,24.46) v1(24.74,24.27) v1(25.5,3.12) v1(27.21,34.49) v1(27.21,33.86) v1(27.21,33.22) v1(27.21,28.65) v1(27.21,28.01) v1(27.21,27.38) v1(27.53,2.87) v1(27.66,34.17) v1(27.66,33.54) v1(27.66,28.33) v1(27.66,27.7) v1(27.79,36.9) v1(27.79,35.89) v1(27.91,22.3) v1(27.91,20.9) v1(28.1,34.49) v1(28.1,33.86) v1(28.1,33.22) v1(28.1,28.65) v1(28.1,28.01) v1(28.1,27.38) v1(28.55,35.89) v1(28.8,20.9) v1(28.93,25.73) v1(29.56,67.13) v1(29.82,2.87) v1(30.33,49.6) v1(30.33,49.03) v1(30.58,24.84) v1(31.09,67.13) v1(31.85,49.6) v1(32.36,1.6) v1(32.48,49.6) v1(32.48,45.41) v1(32.48,44.52) v1(32.61,67.13) v1(32.65,28.11) v1(32.99,64.27) v1(32.99,35.38) v1(33.12,62.43) v1(33.75,62.43) v1(34.01,17.73) v1(34.01,15.06) v1(34.14,67.64) v1(34.69,56.21) v1(34.69,54.68) v1(35.02,19.63) v1(35.02,17.73) v1(35.02,15.69) v1(35.41,1.6) v1(35.66,67.64) v1(35.66,13.6) v1(35.66,13.03) v1(35.66,12.46) v1(36.23,13.6) v1(36.23,13.03) v1(36.23,12.46) v1(36.8,13.6) v1(36.8,13.03) v1(36.8,12.46) v1(37.18,67.64) v1(37.37,13.6) v1(37.37,13.03) v1(37.37,12.46) v1(37.69,1.34) v1(37.95,13.6) v1(37.95,13.03) v1(37.95,12.46) v1(38.58,13.54) v1(38.58,12.52) v1(38.58,11.38) v1(38.71,67.64) v1(39.22,52.65) v1(39.34,44.27) v1(39.72,7.19) v1(39.72,4.9) v1(39.72,3.38) v1(39.72,1.34) v1(40.23,67.64) v1(40.74,33.47) v1(40.99,37.79) v1(41.76,68.15) v1(42.01,1.34) v1(42.2,9.22) v1(42.52,48.46) v1(43.09,9.22) v1(43.15,61.03) v1(43.28,68.15) v1(43.28,37.79) v1(43.98,9.22) v1(44.3,11.31) v1(44.49,34.17) v1(44.55,60.78) v1(44.68,22.3) v1(44.68,21.58) v1(44.8,68.15) v1(44.8,9.54) v1(44.8,8.96) v1(44.8,8.39) v1(45.12,12.46) v1(45.18,11.31) v1(45.38,9.54) v1(45.38,8.96) v1(45.38,8.39) v1(45.95,9.54) v1(45.95,8.96) v1(45.95,8.39) v1(46.15,36.32) v1(46.15,35.56) v1(46.15,34.8) v1(46.2,31.06) v1(46.2,29.79) v1(46.28,26.13) v1(46.28,25.22) v1(46.33,68.15) v1(46.52,9.54) v1(46.52,8.96) v1(46.52,8.39) v1(46.71,35.91) v1(46.71,35.15) v1(46.71,30.45) v1(46.84,25.68) v1(46.84,24.76) v1(46.84,22.93) v1(46.84,21.92) v1(47.09,9.54) v1(47.09,8.96) v1(47.09,8.39) v1(47.22,29.79) v1(47.27,35.56) v1(47.27,34.8) v1(47.39,26.13) v1(47.39,25.22) v1(47.47,6.3) v1(47.47,5.53) v1(48.11,68.15) v1(48.11,66.62) v1(48.11,65.1) v1(48.11,63.32) v1(48.07,50.75) v1(48.11,6.3) v1(48.11,5.53) v1(48.11,4.52) v1(48.11,3.12) v1(48.11,1.09) v1(48.99,8.96) v1(49.25,31.95) v1(49.53,27.51) v1(50.01,43.25) v1(50.01,9.85) v1(50.9,24.97) v1(51.03,10.36) v1(51.53,50.32) v1(51.53,15.19) v1(51.53,14.55) v1(52.3,10.49) v1(52.42,25.03) v1(52.93,50.31) v1(53.19,25.03) v1(53.44,39.7) v1(53.44,39.06) v1(53.57,10.36) v1(54.07,39.7) v1(54.07,39.06) v1(54.2,22.04) v1(54.27,19.19) v1(54.27,18.62) v1(54.27,18.04) v1(54.58,15.19) v1(54.58,14.55) v1(54.71,47.44) v1(54.71,15.95) v1(54.71,9.85) v1(54.84,36.01) v1(54.84,34.49) v1(54.84,19.19) v1(55.41,18.62) v1(55.6,35.25) v1(55.6,15.95) v1(55.6,8.96) v1(55.83,52.98) v1(56.3,29.47) v1(56.23,7.44) v1(56.36,34.49) v1(56.36,5.66) v1(56.36,4.14) v1(56.36,2.61) v1(56.49,1.09) v1(56.74,67.38) v1(56.74,66.11) v1(56.74,64.84) v1(56.74,63.7) v1(56.74,62.56) v1(56.74,61.32) v1(57.5,68.4) v1(57.57,26.36) v1(58.01,1.09) v1(58.14,41.22) v1(58.27,21.66) v1(59.03,68.15) v1(59.03,21.66) v1(59.15,50.49) v1(59.54,1.09) v1(59.79,49.86) v1(59.79,48.84) v1(59.79,48.33) v1(59.79,47.83) v1(59.79,47.32) v1(59.79,46.81) v1(59.79,46.3) v1(59.79,45.79) v1(59.79,45.29) v1(59.79,44.78) v1(59.79,44.27) v1(59.79,43.76) v1(60.3,49.86) v1(60.3,49.35) v1(60.3,48.84) v1(60.3,48.33) v1(60.3,47.83) v1(60.3,47.32) v1(60.3,46.81) v1(60.3,46.3) v1(60.3,45.79) v1(60.3,45.29) v1(60.3,44.78) v1(60.3,44.27) v1(60.3,43.76) v1(60.42,56.59) v1(60.55,68.15) v1(60.55,21.66) v1(60.81,49.86) v1(60.81,49.35) v1(60.81,48.84) v1(60.81,48.33) v1(60.81,47.83) v1(60.81,47.32) v1(60.81,46.81) v1(60.81,46.3) v1(60.81,45.79) v1(60.81,45.29) v1(60.81,44.78) v1(60.81,44.27) v1(60.81,43.76) v1(60.81,36.46) v1(61.06,1.09) v1(61.31,49.86) v1(61.31,49.35) v1(61.31,48.84) v1(61.31,48.33) v1(61.31,47.83) v1(61.31,47.32) v1(61.31,46.81) v1(61.31,46.3) v1(61.31,45.79) v1(61.31,45.29) v1(61.31,44.78) v1(61.31,44.27) v1(61.31,43.76) v1(61.31,21.66) v1(61.36,33.42) v1(61.36,32.2) v1(61.5,26.05) v1(61.63,25.35) v1(61.82,49.86) v1(61.82,49.35) v1(61.82,48.84) v1(61.82,48.33) v1(61.82,47.83) v1(61.82,47.32) v1(61.82,46.81) v1(61.82,46.3) v1(61.82,45.79) v1(61.82,45.29) v1(61.82,44.78) v1(61.82,44.27) v1(61.82,43.76) v1(61.89,36.46) v1(61.97,32.81) v1(61.97,31.6) v1(62.08,68.15) v1(62.25,57.15) v1(62.33,49.35) v1(62.33,48.84) v1(62.33,48.33) v1(62.33,47.83) v1(62.33,47.32) v1(62.33,46.81) v1(62.33,46.3) v1(62.33,45.79) v1(62.33,45.29) v1(62.33,44.78) v1(62.33,44.27) v1(62.33,43.76) v1(62.33,21.66) v1(62.52,26.62) v1(62.58,33.42) v1(62.58,32.2) v1(62.58,30.99) v1(62.58,1.09) v1(62.84,56.61) v1(62.84,49.86) v1(62.84,49.35) v1(62.84,48.84) v1(62.84,48.33) v1(62.84,47.83) v1(62.84,47.32) v1(62.84,46.81) v1(62.84,46.3) v1(62.84,45.79) v1(62.84,45.29) v1(62.84,44.78) v1(62.84,44.27) v1(62.84,43.76) v1(62.84,38.3) v1(62.89,10.87) v1(63.09,26.62) v1(63.19,32.81) v1(63.19,31.6) v1(63.35,49.35) v1(63.35,48.84) v1(63.35,48.33) v1(63.35,47.83) v1(63.35,47.32) v1(63.35,46.81) v1(63.35,46.3) v1(63.35,45.79) v1(63.35,45.29) v1(63.35,44.78) v1(63.35,44.27) v1(63.35,43.76) v1(63.35,21.66) v1(63.6,68.15) v1(63.6,36.52) v1(63.79,63.57) v1(63.8,33.42) v1(63.8,32.2) v1(63.8,30.99) v1(63.75,11.61) v1(63.85,49.86) v1(63.85,49.35) v1(63.85,48.84) v1(63.85,48.33) v1(63.85,47.83) v1(63.85,47.32) v1(63.85,46.81) v1(63.85,46.3) v1(63.85,45.79) v1(63.85,45.29) v1(63.85,44.78) v1(63.85,44.27) v1(63.85,43.76) v1(64.11,1.09) v1(64.3,38.3) v1(64.36,49.86) v1(64.36,49.35) v1(64.36,48.84) v1(64.36,48.33) v1(64.36,47.83) v1(64.36,47.32) v1(64.36,46.81) v1(64.36,46.3) v1(64.36,45.79) v1(64.36,45.29) v1(64.36,44.78) v1(64.36,44.27) v1(64.36,43.76) v1(64.57,58.7) v1(64.87,49.86) v1(64.87,49.35) v1(64.87,48.84) v1(64.87,48.33) v1(64.87,47.83) v1(64.87,47.32) v1(64.87,46.81) v1(64.87,46.3) v1(64.87,45.79) v1(64.87,45.29) v1(64.87,44.78) v1(64.87,44.27) v1(64.87,43.76) v1(64.87,20.39) v1(64.87,19.38) v1(64.97,59.92) v1(64.97,59.1) v1(65.12,68.15) v1(65.38,60.32) v1(65.38,59.51) v1(65.38,49.86) v1(65.38,49.35) v1(65.38,48.84) v1(65.38,48.33) v1(65.38,47.83) v1(65.38,47.32) v1(65.38,46.81) v1(65.38,46.3) v1(65.38,45.79) v1(65.38,45.29) v1(65.38,44.78) v1(65.38,44.27) v1(65.38,43.76) v1(65.38,4.77) v1(65.63,1.34) v1(65.78,59.92) v1(65.78,59.1) v1(65.76,28.06) v1(65.89,49.86) v1(65.89,49.35) v1(65.89,48.84) v1(65.89,48.33) v1(65.89,47.83) v1(65.89,47.32) v1(65.89,46.81) v1(65.89,46.3) v1(65.89,45.79) v1(65.89,45.29) v1(65.89,44.78) v1(65.89,44.27) v1(65.89,43.76) v1(66.14,62.68) v1(66.77,63.57) v1(66.9,67.89) v1(67.16,1.34) v1(67.51,64.34) v1(67.92,36.17) v1(68.43,67.89) v1(68.68,1.34) v1(69.7,49.22) v1(69.95,67.89) v1(69.95,18.67) v1(70.2,39.06) v1(70.2,1.34) v1(70.5,19.22) v1(70.71,51.51) v1(70.71,50.68) v1(70.71,49.86) v1(70.71,30.3) v1(70.71,29.66) v1(71.21,19.93) v1(71.47,67.89) v1(71.73,1.6) v1(71.98,27.12) v1(72.11,16.16) v1(72.74,27.12) v1(72.83,16.88) v1(73,67.89) v1(73.25,1.6) v1(73.51,50.59) v1(73.51,49.86) v1(73.55,17.6) v1(74.52,67.38) v1(74.52,49.86) v1(74.78,1.6) v1(75.54,50.75) v1(75.54,49.98) v1(75.66,13.66) v1(75.79,2.36) v1(76.05,66.88) v1(77.19,49.86) v1(77.32,2.61) v1(77.57,66.88) v1(78.81,19.56) v1(78.84,2.61) v1(79.09,66.62) v1(79.35,39.1) v1(79.6,59.76) v1(79.6,54.43) v1(79.6,53.79) v1(79.6,53.16) v1(79.6,52.52) v1(79.98,13.66) v1(80.11,39.1) v1(80.24,60.4) v1(80.24,59.76) v1(80.24,59.13) v1(80.24,55.06) v1(80.24,54.43) v1(80.24,53.79) v1(80.24,53.16) v1(80.24,50.24) v1(80.36,2.87) v1(80.62,66.37) v1(80.87,61.03) v1(80.87,60.4) v1(80.87,59.76) v1(80.87,59.13) v1(80.87,55.06) v1(80.87,54.43) v1(80.87,53.16) v1(80.87,52.52) v1(80.87,50.24) v1(80.87,49.6) v1(81.38,62.05) v1(81.51,54.43) v1(81.51,53.79) v1(81.51,53.16) v1(81.51,50.24) v1(81.89,2.87) v1(82.01,65.73) v1(82.14,55.06) v1(82.14,54.43) v1(82.14,53.79) v1(82.14,53.16) v1(82.14,52.52) v1(82.27,62.81) v1(82.4,66.49) v1(82.4,64.97) v1(83.41,2.36) v1(84.1,57.1) v1(84.3,50.62) v1(84.3,49.86) v1(84.94,2.36) v1(85.19,49.86) v1(86.08,50.62) v1(86.08,49.86) v1(86.46,2.61) v1(86.59,43.76) v1(86.97,49.86) v1(87.09,60.02) v1(87.09,59.38) v1(87.22,43.76) v1(87.6,43.25) v1(87.6,42.49) v1(87.6,41.73) v1(87.73,60.02) v1(87.73,59.38) v1(87.86,50.62) v1(87.86,49.86) v1(87.86,43.76) v1(87.98,2.61) v1(88.36,60.02) v1(88.36,59.38) v1(89,60.02) v1(89,59.38) v1(89.63,60.02) v1(89.63,59.38) v1(89.63,2.99) v1(90.14,47.06) v1(90.27,60.02) v1(90.27,59.38) v1(90.52,48.08) v1(90.9,47.06) v1(91.16,2.99) v1(91.6,47.06) v1(92.37,47.06) v1(94.33,52.78) v1(94.33,52.14) v1(94.33,51.51) v1(94.33,50.87) v1(94.33,50.24) v1(94.38,29.99) v1(94.97,52.78) v1(94.97,52.14) v1(94.97,51.51) v1(94.97,50.87) v1(94.97,50.24) v1(95.35,48.08) v1(95.35,47.32) v1(95.35,46.56) v1(95.6,52.78) v1(95.6,52.14) v1(95.6,51.51) v1(95.6,50.87) v1(95.6,50.24) v1(95.98,48.08) v1(95.98,47.32) v1(95.98,46.56) v1(96,30.53) v1(96.24,52.78) v1(96.24,52.14) v1(96.24,51.51) v1(96.24,50.87) v1(96.24,50.24) v1(96.68,39.13) v1(96.87,52.14) v1(96.87,51.51) v1(96.87,50.87) v1(96.87,50.24) v1(97.25,39.13) v1(97.25,33.79) v1(97.36,30.99) v1(97.51,29.79) v1(97.83,39.13) v1(98.02,4.01) v1(98.91,28.27) v1(99.54,4.01) v1(99.79,47.06) v1(99.73,36.97) v1(100.43,6.17) v1(100.56,47.06) v1(100.81,48.08) v1(100.94,33.73) v1(101.19,4.26) v1(101.32,47.06) v1(102.08,47.06) v1(102.46,7.19) v1(103.2,26.77) v1(103.99,8.46) v1(104.56,29.47) v1(105,6.93) v1(105.26,4.9) v1(105.51,9.47) v1(106.91,22.81) v1(106.91,5.79) v2(21.44,44.78) v2(21.44,42.49) v2(29.34,56.26) v2(29.34,54.89) v2(30.07,44.8) v2(30.07,42.47) v2(36.24,25.09) v2(37.51,33.47) v2(38.07,58.9) v2(38.63,25.07) v2(39.9,33.47) v2(41.63,58.93) v2(41.63,56.54) v2(41.63,46.96) v2(41.63,44.63) v2(52.91,46.81) v2(52.91,44.4) v2(53.62,50.87) v2(55.29,52.5) v2(55.98,57.93) v2(56.74,59.81) v2(58.65,57.78) v2(59.18,55.6) v2(72.87,30.55) v2(76.8,28.9) v2(84.31,15.03) v2(86.34,13.97) v2(88.52,38.53) v2(89.46,21.89) v2(91.66,8.8) v2(92.23,9.37) v2(94.08,36.52) v2(94.12,31.32)
PGND: length 26.7
  TOP w0.254: 104.37,45.67 U16.B2 104.75,45.1
  TOP w0.305: R749.2 107.1,59.76 ; R749.2 106.54,59.23 ; R749.2 107.66,59.23 ; C280.2 104.51,44.99
  TOP w0.406: P516.5 103.75,33.37 v1(103.6,33.22) ; P519.5 103.84,51.15 v1(103.73,51.25) ; 103.86,44.46 C280.2 C281.2 103.86,43.44
  TOP w0.508: 105.51,40.59 R744.2 106.04,40.03
  TOP w0.635: 102.14,52.21 C326.2 ; C326.2 103.54,52.21 ; C326.2 102.84,51.57 ; 105.12,62.88 C313.2 104.18,62.84 ; C312.2 100.21,59 ; C312.2 99.22,58.01 ; C312.2 100.17,58.06 ; 103.94,62.64 v1(102.21,60.91) 100.47,59.17
  BOTTOM w0.305: 106.35,59.4 R190.2 106.36,58.69 ; 101.99,59.25 R191.1 102,58.54 ; 103.87,61.13 R192.2 104.58,61.12
  BOTTOM w0.406: v1(103.1,33.22) v1(103.6,33.22) 103.6,32.97 ; v1(103.1,33.22) v1(103.1,32.71) v1(103.6,32.71) 103.6,32.97 ; v1(103.1,33.22) 103.35,32.97 103.6,32.97
  BOTTOM w0.635: 105.57,38.3 C325.2 104.94,39
  vias: v1(95.22,58.68) v1(95.22,58.05) v1(95.86,58.68) v1(95.86,58.05) v1(96.49,58.68) v1(96.49,58.05) v1(97.13,58.68) v1(97.13,58.05) v1(97.76,58.68) v1(97.76,58.05) v1(100.24,57.73) v1(100.62,60.08) v1(100.75,58.3) v1(101,60.46) v1(101.06,59.76) v1(101.38,60.84) v1(101.45,60.14) v1(101.45,59.38) v1(101.59,56.64) v1(101.76,61.22) v1(101.83,60.53) v1(101.83,59.76) v1(101.83,52.14) v1(102.14,61.61) v1(102.21,60.14) v1(102.53,61.99) v1(102.59,61.29) v1(102.59,60.53) v1(102.91,62.37) v1(102.84,51.25) v1(102.97,61.67) v1(102.97,60.91) v1(103.35,62.05) v1(103.35,61.29) v1(103.73,61.67) v1(103.73,52.14) v1(103.8,44.46) v1(103.8,43.44) v1(104.05,46.05) v1(104.05,45.29) v1(105.26,40.84) v1(105.26,40.21) v1(105.26,39.57) v1(105.89,39.57) v1(107.22,60.72) v1(107.22,60.02) v1(107.99,60.02) v1(107.99,59.19)
VCCPINT: length 17.9
  TOP w0.305: 82.59,28.19 v2(82.59,28.75) ; 83.72,24.79 v2(83.72,24.23) ; U511.E10 v2(80.9,25.92) 81.46,25.92 ; U511.L10 v2(83.72,29.88) ; 84.85,24.79 v2(84.85,24.23) ; U511.K5 v2(86.55,25.92) ; 81.46,27.06 v2(80.9,27.06)
  BOTTOM w0.305: C672.1 86.16,25.53 v2(86.55,25.92)
  BOTTOM w0.406: v2(80.9,27.06) 81.32,26.63 C673.1 80.9,26.13 v2(80.9,25.92) 81.35,25.47 C674.1 ; 84.3,24.8 84.3,24.78 v2(84.85,24.23) ; 84.3,24.8 C669.1 ; 84.3,24.8 v2(83.72,24.23) ; v2(83.72,29.88) 84.74,29.88 84.82,29.96 C671.1 ; C665.1 82.16,28.32 v2(82.59,28.75)
  BOTTOM w0.508: 84.3,43.89 84.37,43.89 C667.1
  BOTTOM w0.635: VCCPINT.1 81.38,42.36
  BOTTOM w0.762: 81.76,46.36 C279.1
  BOTTOM w1.016: 82.23,41.6 C670.1 83.28,42.86 ; 82.9,46.68 E26.2 83.73,45.79
  vias: v1(81.13,44.4) v1(81.13,43.76) v1(81.76,44.4) v1(81.76,43.76) v1(82.4,44.4) v1(82.4,43.76) v1(83.03,44.4) v1(83.03,43.76) v1(83.67,44.4) v1(83.67,43.76) v1(84.3,44.4) v1(84.3,43.76)
VCCPLL: length 12.7
  TOP w0.305: U511.F5 v2(83.72,23.1)
  BOTTOM w0.152: v2(83.72,23.1) 83.6,22.97 83.6,22.4 83.16,21.96 82.59,21.96 82.59,22.51 83,22.93 83.57,22.93
  BOTTOM w0.406: v2(83.72,23.1) 83.57,22.93
  BOTTOM w0.508: E677.2 78.13,15.71 78.13,16.34 79.5,17.71 79.5,18.7 81.49,20.69 C686.1 81.57,20.94 82.59,21.96
VIN: length 55.2
  TOP w0.203: 98.96,32.03 U509.10 99.16,31.33
  TOP w0.254: R88.1 v1(76.81,58.56)
  TOP w0.305: R638.1 97.84,31.95 v1(98.17,31.62) ; U6.26 U6.27 84.02,53.04 ; U6.26 U6.25 ; U6.26 84.02,52.54 ; v1(90.14,53.92) 90.4,54.18 R517.1 ; U518.25 98.75,49.76 ; U518.25 U518.26 ; U518.25 98.14,49.67 98.14,49.48 98.4,49.22 ; U6.25 84.02,52.04 ; U6.25 83.32,51.73 83.54,51.51 ; 77.72,52.54 U6.15 ; U6.15 U6.14 77.72,53.04 ; U6.15 U6.16 ; U518.26 98.75,50.26 ; U518.26 U518.27 98.89,50.76 99.03,50.62 v1(99.03,50.49) ; 92.45,50.26 U518.15 ; U518.15 U518.16 ; U518.15 U518.14 92.31,50.76 92.17,50.62 v1(92.17,50.49) ; U518.16 93.03,49.64 93.03,49.44 92.83,49.24 ; U518.16 92.45,49.76 ; 98.78,31.32 C648.2 98.17,31.36 ; DS11.A v1(107.29,18.36) ; 78.42,51.64 U6.16 ; U6.16 77.72,52.04 ; 83.92,65.1 E4.1 84.81,64.27 ; 83.35,65.27 C4.1 83.76,65.73 ; R3.1 v1(56.23,53.79)
  TOP w0.508: DS12.A v1(107.16,10.11)
  TOP w0.635: 89.63,50.05 C742.1 90.33,49.41 ; 84.49,52.08 C178.1 ; C178.1 85.89,52.08 ; C178.1 85.19,52.72 ; 73.82,52.08 C183.1 ; C183.1 74.52,52.72 ; C183.1 75.22,52.08 ; C738.1 91.41,50.05 ; C738.1 90.71,49.41 ; C738.1 92.11,49.41 ; C190.1 76.55,52.72 ; C190.1 77.25,52.08 ; C190.1 75.85,52.08 ; 86.27,52.08 C187.1 ; C187.1 87.67,52.08 ; C187.1 86.97,52.72 ; 101.83,50.05 C740.1 101.13,49.41 ; C737.1 100.49,49.41 ; C737.1 99.1,49.41 ; C737.1 99.79,50.05
  TOP w0.762: 86.68,63.13 C321.1 ; C321.1 87.73,64.03 ; C321.1 88.78,63.13 ; C320.1 90.14,64.03 ; C320.1 89.09,63.13 ; C320.1 91.2,63.13
  BOTTOM w0.305: v1(98.17,31.62) 98.4,31.39 R640.1 ; v1(86.33,63.89) 86.65,63.57 VIN.1 ; v1(99.03,50.49) 98.48,50.49 R750.2
  BOTTOM w0.508: v1(76.55,52.91) 76.81,53.16 v1(76.81,58.56)
  vias: v1(73.51,52.91) v1(73.51,52.21) v1(74.52,52.91) v1(75.54,52.91) v1(75.54,52.02) v1(84.43,52.91) v1(85.06,65.16) v1(85.06,64.53) v1(85.06,63.89) v1(85.19,52.91) v1(85.7,65.16) v1(85.7,64.53) v1(85.7,63.89) v1(86.08,52.91) v1(86.08,52.02) v1(86.33,65.16) v1(86.33,64.53) v1(86.97,64.53) v1(86.97,52.91) v1(87.6,64.53) v1(87.86,52.91) v1(87.86,52.02) v1(89.63,50.49) v1(90.27,50.49) v1(90.52,49.35) v1(90.9,50.49) v1(91.54,50.49) v1(98.62,32.07) v1(99.67,50.49) v1(100.3,50.49) v1(100.81,49.86) v1(100.81,49.22) v1(100.94,50.49)
